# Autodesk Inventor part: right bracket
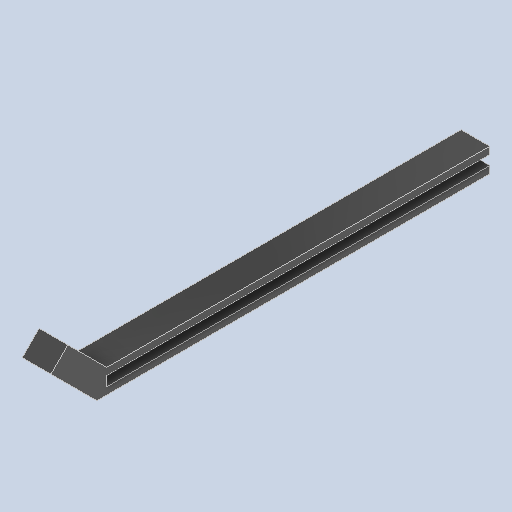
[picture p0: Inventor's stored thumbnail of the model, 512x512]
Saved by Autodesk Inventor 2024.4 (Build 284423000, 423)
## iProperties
Created: 2025-04
Part Number: right bracket
Material: Generic
Document SubType Name: Modeling
Designer: AdminForWorker
Density: 1 g/cm^3
Appearance: Default
Title: right bracket v1
Author: AdminForWorker
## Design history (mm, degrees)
feature "Body4"
body "Solid1"
